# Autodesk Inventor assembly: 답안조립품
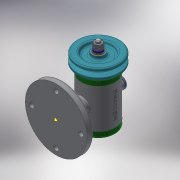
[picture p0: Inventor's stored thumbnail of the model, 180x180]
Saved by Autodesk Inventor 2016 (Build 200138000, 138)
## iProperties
Created: 2018-12
Part Number: 답안조립품
Material: 일반
Document SubType Name: Assembly
Designer: 605-11
Author: 605-11
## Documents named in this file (15)
- C:\Users\605-11\Desktop\481208V1006\답안조립품.iam
- C:\Users\605-11\Desktop\481208V1006\본체.ipt
- C:\Users\605-11\Desktop\481208V1006\고무캡.ipt
- C:\Users\605-11\Desktop\481208V1006\축.ipt
- C:\Users\605-11\Desktop\481208V1006\키 3 x 3 x 12.ipt
- C:\Users\605-11\Desktop\481208V1006\V벨트풀리.ipt
- C:\Users\605-11\Desktop\481208V1006\베어링 15 x 32 x 9.ipt
- C:\Users\605-11\Desktop\481208V1006\스프링와셔 8.ipt
- C:\Users\605-11\Desktop\481208V1006\오일 실 15 25 7.ipt
- C:\Users\605-11\Desktop\481208V1006\와셔 8x17.ipt
- C:\Users\605-11\Desktop\481208V1006\뒤커버.ipt
- C:\Users\605-11\Desktop\481208V1006\앞커버.ipt
- C:\Users\605-11\Desktop\481208V1006\너트 M8.ipt
- 너트 M8.ipt
- C:\Users\605-11\Desktop\481208V1006\볼트 M4 x 12.ipt
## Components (2 placed, 2 different names)
1. 고무캡:1
2. V벨트풀리:1 — 각도:2
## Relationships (1: Angle 1)
- 각도:2 [Angle]: V벨트풀리:1
